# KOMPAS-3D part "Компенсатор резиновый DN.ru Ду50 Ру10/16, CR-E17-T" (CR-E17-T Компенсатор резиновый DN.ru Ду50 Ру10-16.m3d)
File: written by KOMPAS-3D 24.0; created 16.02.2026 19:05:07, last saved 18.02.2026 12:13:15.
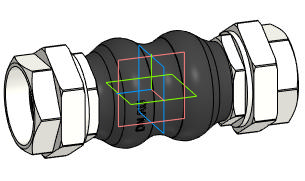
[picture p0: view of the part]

Document properties: Автор: DN.RU; Полное имя файла: CR-E17-T Компенсатор резиновый DN.ru Ду50 Ру10-16.cdw

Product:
- Body: Твердое тело1  | qty 1
    Масса: 2.752084
- Part/product: Компенсатор резиновый DN.ru Ду50 Ру10/16  | designation CR-E17-T
    Масса: 2.6
    Раздел спецификации: Прочие изделия
    Форматы листов документа: A3
    Комментарий: D140-02214
    Примечание: D140-02214
    additional columns: Типовые

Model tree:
1. Твердое тело1  (labels: Твердое тело1)

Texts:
  CR-E17-T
